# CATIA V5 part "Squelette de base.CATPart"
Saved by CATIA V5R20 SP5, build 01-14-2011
Part number: Squelette de base
Publications: "Point.1", "Point.2", "Point.3", "Point.4", "Plan.1", "Plan.2", "Plan.3"
Bounding box of the stored display mesh (mm): x 0 to 0, y 0 to 280, z 10 to 50
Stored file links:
  F:\IAO_bmadec\bmadecf\Squelette de base.CATPart
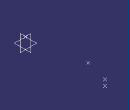
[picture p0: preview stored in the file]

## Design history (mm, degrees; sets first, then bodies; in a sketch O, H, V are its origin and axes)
Set1
  Point1: (0, 0, 20)
  Point2: (0, 220, 50)
  Point3: (0, 280, 30)
  Point4: (0, 280, 10)
  Plane1: type Offset, RefPlane xy-plane, Offset 0
  Plane2: type Offset, RefPlane yz-plane, Offset 0
  Plane3: type Offset, RefPlane zx-plane, Offset 0
Body1 (main body)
